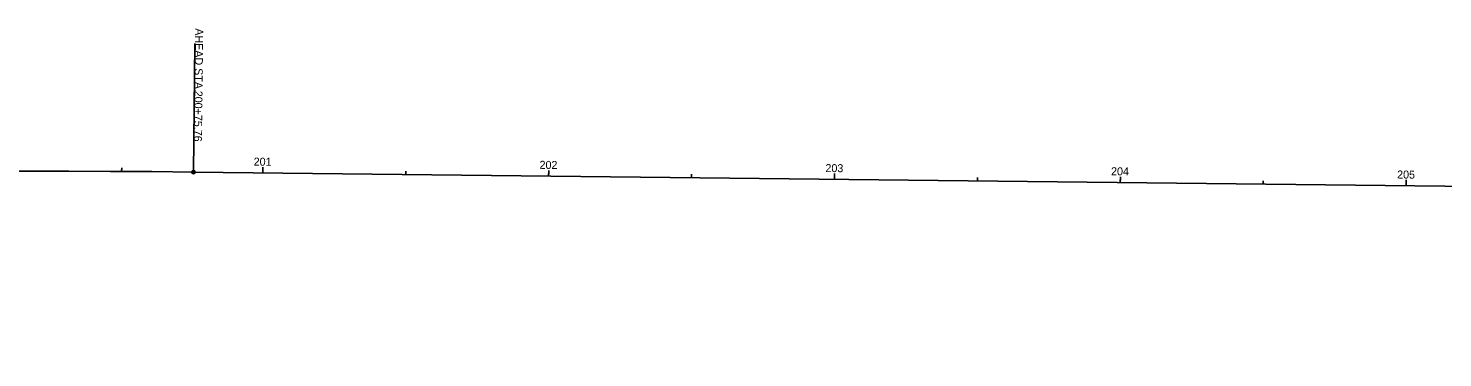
# Model space of a CAD drawing. Extents: x 1501024 to 1508874, y 327839 to 328839.
# Drawn here: x 1507888.2 to 1508383, y 328197.9 to 328313 of the extents above; entities that cross this region are included whole.
import ezdxf

# ---------------------------------------------------------------- set-up
doc = ezdxf.new("R2010")
doc.units = 0
for name, color, linetype in [('GE_X_Alignment', 7, 'Continuous'), ('GE_X_Alignment_100_Cardinal_Points', 7, 'Continuous'), ('GE_X_Alignment_100_Stations', 7, 'Continuous'), ('GE_X_Alignment_500_Cardinal_Points', 7, 'Continuous'), ('GE_X_Alignment_500_Stations', 7, 'Continuous')]:
    doc.layers.add(name, color=color, linetype=linetype)

msp = doc.modelspace()

# ---------------------------------------------------------------- linework, layer by layer
at = {"layer": 'GE_X_Alignment'}
msp.add_line((1507946.04, 328262.76), (1508870.22, 328252.36), dxfattribs=at)
msp.add_arc((1507881.6, 322533.59), 5729.53, 89.35563, 98.65563, dxfattribs=at)
at = {"layer": 'GE_X_Alignment_100_Cardinal_Points'}
msp.add_line((1507946.04, 328262.76), (1507946.54, 328307.76), dxfattribs=at)
msp.add_circle((1507946.04, 328262.76), 0.6, dxfattribs=at)
at = {"layer": 'GE_X_Alignment_100_Stations'}
for p, q in [((1507920.9, 328262.99), (1507920.91, 328264.19)), ((1507970.27, 328262.49), (1507970.3, 328264.49)), ((1508070.27, 328261.36), (1508070.29, 328263.36)), ((1508020.27, 328261.92), (1508020.28, 328263.12)), ((1508120.26, 328260.8), (1508120.28, 328262)), ((1508170.26, 328260.24), (1508170.28, 328262.24)), ((1508220.26, 328259.67), (1508220.27, 328260.87)), ((1508270.25, 328259.11), (1508270.28, 328261.11)), ((1508320.25, 328258.55), (1508320.27, 328259.75)), ((1508370.25, 328257.99), (1508370.27, 328259.99))]:
    msp.add_line(p, q, dxfattribs=at)
at = {"layer": 'GE_X_Alignment_500_Cardinal_Points'}
msp.add_line((1507946.04, 328262.76), (1507946.54, 328307.76), dxfattribs=at)
msp.add_circle((1507946.04, 328262.76), 0.6, dxfattribs=at)
at = {"layer": 'GE_X_Alignment_500_Stations'}
for p, q in [((1507970.27, 328262.49), (1507970.29, 328263.69)), ((1508070.27, 328261.36), (1508070.28, 328262.56)), ((1508170.26, 328260.24), (1508170.27, 328261.44)), ((1508270.25, 328259.11), (1508270.27, 328260.31)), ((1508370.25, 328257.99), (1508370.27, 328259.99))]:
    msp.add_line(p, q, dxfattribs=at)

# ---------------------------------------------------------------- texts
at = {"layer": 'GE_X_Alignment_100_Cardinal_Points'}
for s, p in [('AHEAD STA. ', (1507946.64, 328313.03)), ('200+75.76', (1507946.39, 328291.21))]:
    msp.add_text(s, height=2.8, rotation=269.3556, dxfattribs=at).set_placement(p)
at = {"layer": 'GE_X_Alignment_100_Stations'}
for s, p in [('201', (1507967.08, 328265.02)), ('202', (1508067.08, 328263.9)), ('203', (1508167.09, 328262.77)), ('204', (1508267, 328261.65)), ('205', (1508367.07, 328260.52))]:
    msp.add_text(s, height=2.8, rotation=359.3556, dxfattribs=at).set_placement(p)
at = {"layer": 'GE_X_Alignment_500_Cardinal_Points'}
for s, p in [('AHEAD STA. ', (1507946.64, 328313.03)), ('200+75.76', (1507946.39, 328291.21))]:
    msp.add_text(s, height=2.8, rotation=269.3556, dxfattribs=at).set_placement(p)
at = {"layer": 'GE_X_Alignment_500_Stations'}
msp.add_text('205', height=2.8, rotation=359.3556, dxfattribs=at).set_placement((1508367.07, 328260.52))

doc.saveas('drawing.dxf')
